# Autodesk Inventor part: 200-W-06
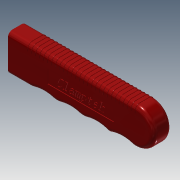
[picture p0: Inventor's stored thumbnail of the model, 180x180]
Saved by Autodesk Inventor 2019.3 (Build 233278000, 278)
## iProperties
Created: 2011-05
Part Number: 200-W-06
Material: Ogólny
Document SubType Name: Modeling
Designer: CADENGINEERING4
Density: 1 g/cm^3
Appearance: Czerwona
Author: CADENGINEERING4
Revision Number: ÈÎºÎ
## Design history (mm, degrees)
feature "Ô²½Ç12"
node "Bryła1"
